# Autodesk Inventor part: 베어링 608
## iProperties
IsCustomPart: 1
Company: 한국ATC센터
Created: 2014-07
Part Number: 베어링 608
Material: 강, 연강
Description: 깊은 그루브 볼 베어링
Document SubType Name: Modeling
Standard: KS B 2023
Designer: KYOUNG IL JANG
Standards Organization: KS
Language: ko-KR
Size Designation: 608 - 8 x 22 x 7
Categories: <MemberInstance><Categories><Category DisplayName="샤프트 부품" InternalName="7f7aeb1f-a693-4053-b835-cee3144e0d98" Mnemonic="SHFT"><Category DisplayName="베어링" Inter
Density: 1 g/cm^3
Author: KYOUNG IL JANG
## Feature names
1. IDS_ARRAYBALL[SIMPL:T] [Circular Pattern]
